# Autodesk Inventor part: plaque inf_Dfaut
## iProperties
Created: 2007-07
Part Number: plaque inf_Dfaut
Document SubType Name: Modeling
Designer: EF
Density: 1 g/cm^3
Author: EF
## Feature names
1. Base1
